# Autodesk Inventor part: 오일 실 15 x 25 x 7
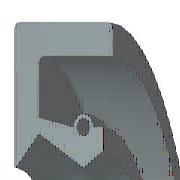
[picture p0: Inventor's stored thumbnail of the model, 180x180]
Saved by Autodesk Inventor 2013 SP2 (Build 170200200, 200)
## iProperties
Created: 2012-02
Part Number: 오일 실 15 x 25 x 7
Material: 고무
Description: 오일-실
Document SubType Name: Modeling
Standard: KS B 2804
Designer: mduedu
Standards Organization: KS
Language: ko-KR
Size Designation: D - 15 25 7
Categories: <MemberInstance><Categories><Category DisplayName="샤프트 부품" InternalName="7f7aeb1f-a693-4053-b835-cee3144e0d98" Mnemonic="SHFT"><Category DisplayName="실링" Intern
Density: 0.93 g/cm^3
IsCustomPart: 1
Author: mduedu
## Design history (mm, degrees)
revolve "본체" stored, may be unused: angle "d17" = 90 deg
revolve "스프링1" stored, may be unused: angle "d18" = 90 deg
body "Solid1"
sketch "스케치1"
  geometry: L1 (0, 12.5)-(7, 12.5); L2 (7, 10.75)-(1.75, 10.75); L3 (1.75, 9.25)-(4.9, 7.5); L4 (4.9, 7.5)-(0, 7.5); L5 (0, 0)-(9.586, 0) reference; L6 (4.9, 7.5)-(6.3, 8.375); L7 (0, 18)-(0, -3) reference; L8 (-1.941, 0)-(11.507, 0) reference; L9 (4.2, 9.6)-(1.75, 10.09); L10 (1.75, 10.09)-(1.75, 10.75); L11 (0, 12.5)-(0, 7.588); L12 (4.9, 7.5)-(0, 7.5); L13 (1.75, 9.25)-(0.152, 7.528); L14 (7, 12.5)-(7, 10.75); L15 (5.6, 9.6)-(6.3, 9.6); L16 (6.3, 9.6)-(6.3, 8.375); C1 r 0.455 at (4.9, 9.6); A1 r 0.7 centre (4.9, 9.6) between (5.6, 9.6) and (4.2, 9.6); A2 r 0.088 centre (0.088, 7.588) between (0, 7.588) and (0.152, 7.528); 1 further point
  constraints: 28 end point, 5 horizontal alignment, 5 point on line, 4 point on circle, 4 vertical alignment, 3 centre point, 3 tangent, 2 collinear, 2 horizontal, 2 perpendicular, 1 coincident, 1 parallel
  dimensions: "d0" = 25 diameter of L1 L5 (= SD2); "d1" = 1.75 distance of L1.end L2.start (= SD); "d2" = 0.91 diameter of C1 (= SPDI); "d3" = 1.4 diameter of A1 (= SPDA); "d4" = 15 diameter of L3.end L5 (= NND); "d5" = 18.5 diameter of L3.start L5 (= TKDM); "d7" = 20.18 diameter of L9.end L5 (= TKDM + 0.24 x SWDT); "d8" = 1.75 distance between parallel lines of L11 L10 (= SD); "d9" = 4.9 distance from line of L11 C1.centre (= SPDST); "d10" = 19.2 diameter of C1.centre L5 (= HLDM); "d11" = 0.0875 radius of A2 (= 0.25 x LAB); "d12" = 6.3 distance between parallel lines of L11 L16 (= SDI); "d13" = 16.75 diameter of L6.end L5 (= ABDM); "d14" = 7 distance from line of L11 L1.end (= SWDT)
fillet "모깎기1" dims "d6" = 0.3 (= RR)
other parameters: "SD2" = 25 [user parameter; used in 1 equation term], "SWDT" = 7 [user parameter; used in 2 equation terms], "RR" = 0.3 [user parameter; used in 1 equation term], "SD" = 1.75 [user parameter; used in 2 equation terms], "NND" = 15 [user parameter; used in 1 equation term], "SPDA" = 1.4 [user parameter; used in 1 equation term], "SPDI" = 0.91 [user parameter; used in 1 equation term], "TKDM" = 18.5 [user parameter; used in 2 equation terms], "HLDM" = 19.2 [user parameter; used in 1 equation term], "ABDM" = 16.75 [user parameter; used in 1 equation term], "SDI" = 6.3 [user parameter; used in 1 equation term], "SPDST" = 4.9 [user parameter; used in 1 equation term], "LAB" = 0.35 [user parameter; used in 1 equation term], "d15" = 0, "d16" = 0, "d19" = 0
